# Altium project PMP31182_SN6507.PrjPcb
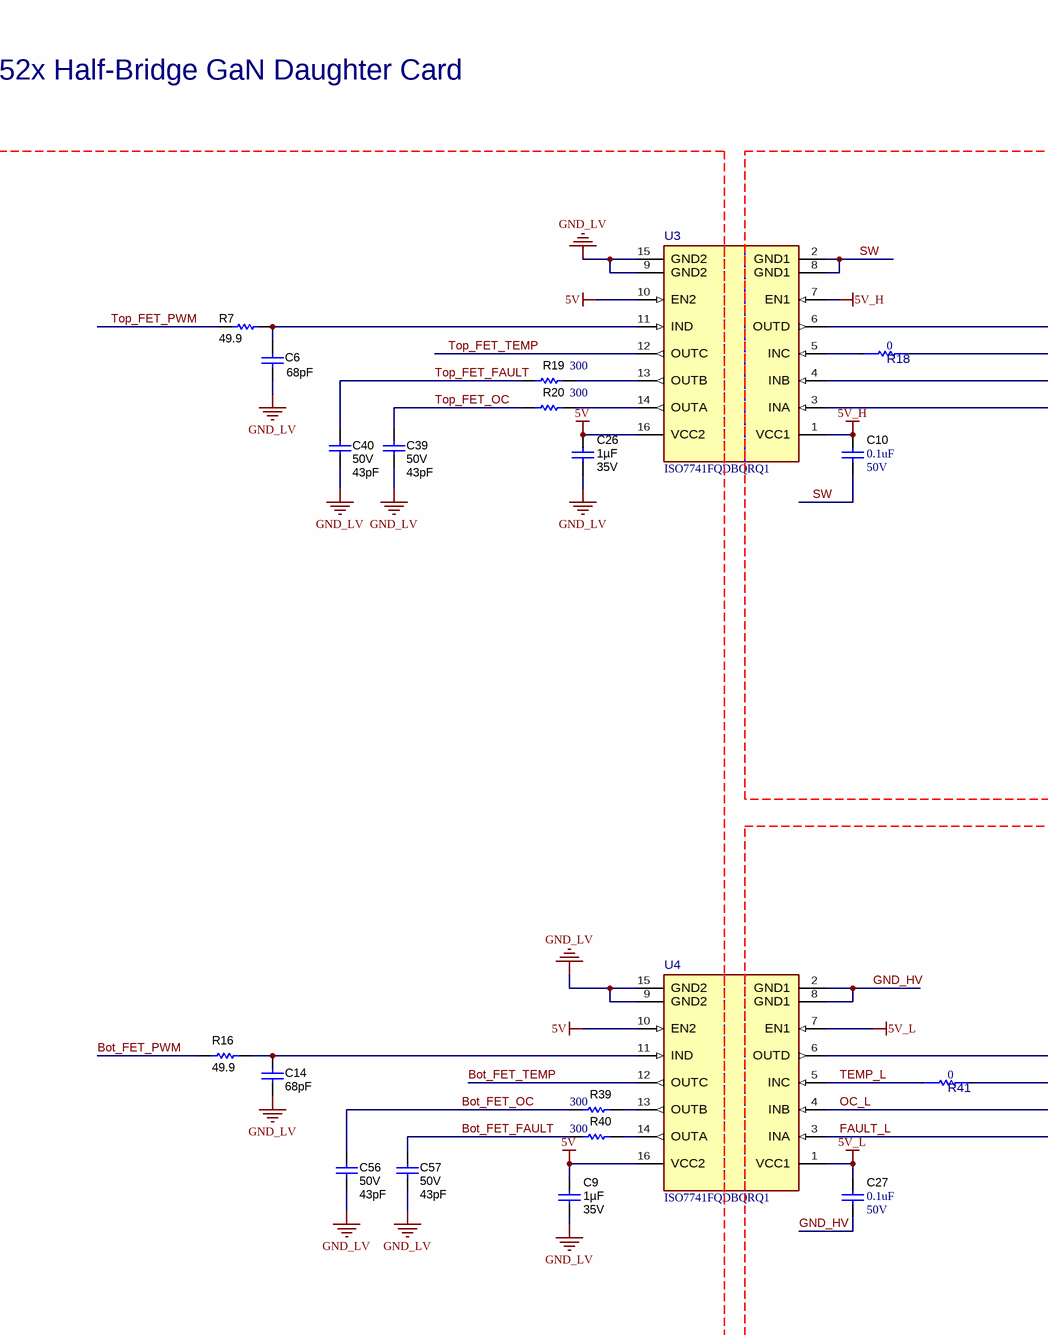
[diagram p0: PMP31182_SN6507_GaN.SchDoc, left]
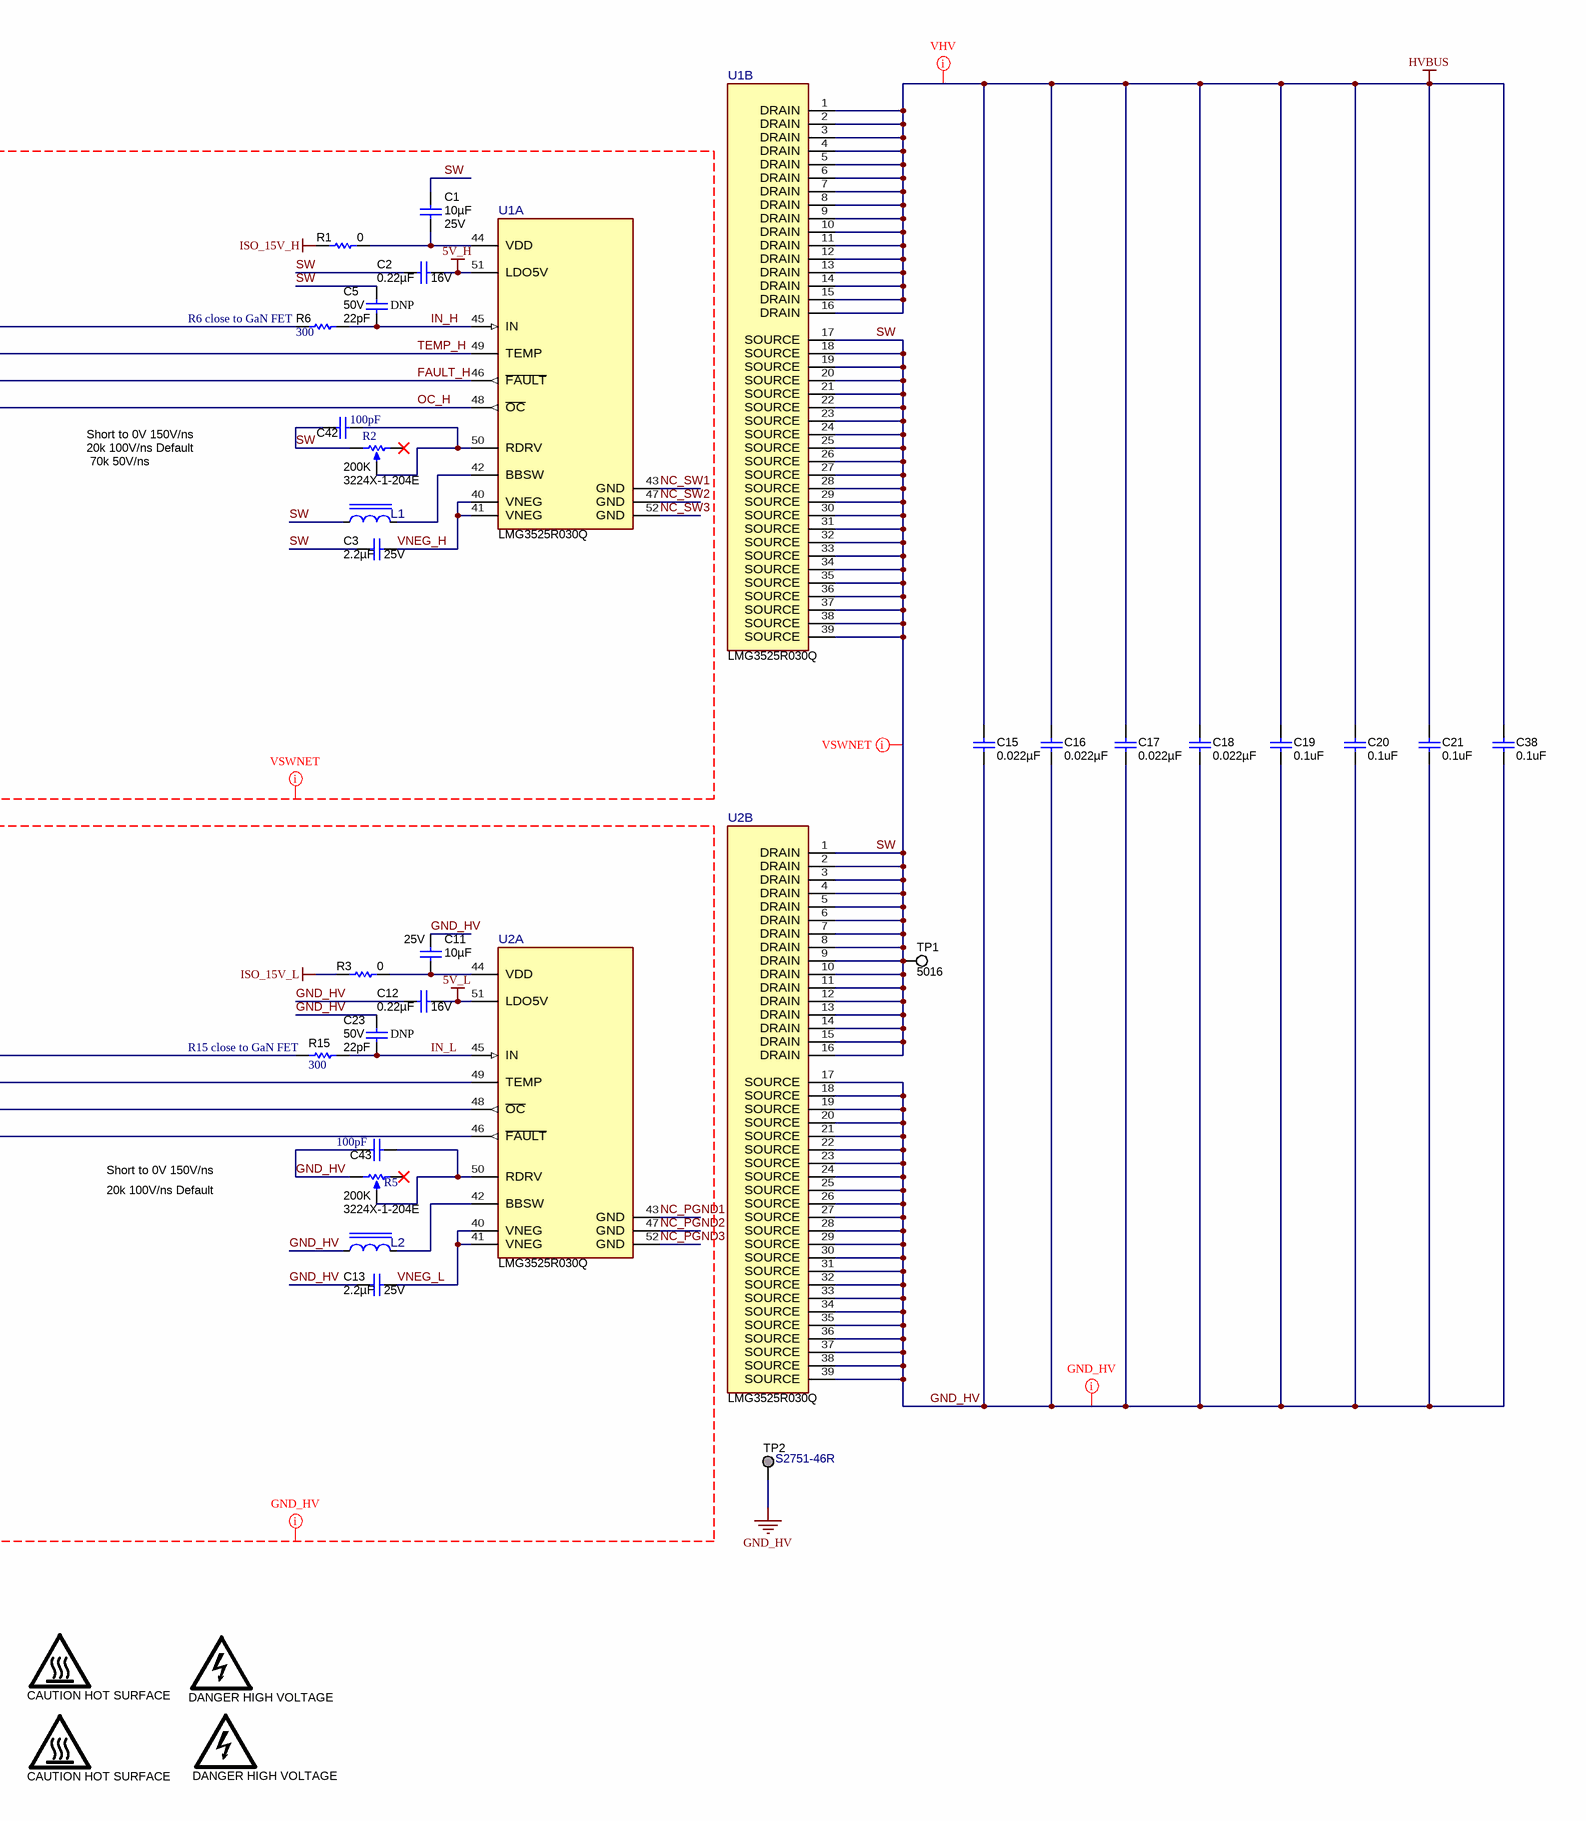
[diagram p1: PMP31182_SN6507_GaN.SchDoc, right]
TID: N/A; TechSupport: http://www.ti.com/support; PRJ_Title: Isolated Bias Power Supply; PRJ_Number: PMP31182; PRJ_Engineer: Prashant Kumar; PRJ_Customer: Public Release; PCB_Layout: Prashant Kumar; CopyrightYear: 2023
3 sheets, 172 parts. Net scope: global (net labels, ports and power ports of the same name join across sheets).
Board file: PMP31182_SN6507_PCB.PcbDoc
Sheets:
  PMP31182_SN6507_GaN.SchDoc
  PMP31182_SN6507_PWM.SchDoc
  PMP31182_SN6507_power_supply.SchDoc

## Sheet PMP31182_SN6507_GaN.SchDoc: SN6507
size A2; Date: Not shown in title block; ApprovedBy: Not shown in title block; CheckedBy: Not shown in title block; Author: Not shown in title block; CompanyName: Not shown in title block; Engineer: Not shown in title block; Organization: Not shown in title block; Address1: Not shown in title block; Address2: Not shown in title block; Address3: Not shown in title block; Address4: Not shown in title block; DocumentNumber: 2; Revision: Use project parameter SCH_Rev; SheetNumber: 2; SheetTotal: 3; PageSetup: Record=PageOptions¦CenterHorizontal=True¦CenterVertical=True¦PrintScale=1.00¦XCorrection=1.00¦YCorrection=1.00¦PrintKind=0¦BorderSize=5000000¦LeftOffset=0¦BottomOffset=0¦Orientation=2¦PaperLength=1000¦PaperWidth=1000¦Scale=100¦PaperSource=15¦PrintQuality=600¦MediaType=1¦DitherType=10¦PaperKind=Letter¦PrintScaleMode=1

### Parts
(Parts that share a designator on the sheet are numbered #1, #2 ... from top to bottom, then left to right.)
C1  VDC_V: 25V  ValueDisplayed: 10µF  [1206_180]  (hidden comment: TMK316AB7106KLHT)
C2  VDC_V: 16V  ValueDisplayed: 0.22µF  [0402]  (hidden comment: GCM155R71C224KE02D)
C3  Cap_F: 2.2µF  VDC_V: 25V  [0805_HV]  (hidden comment: CGA4J3X7R1E225K125AB)
C5  VDC_V: 50V  ValueDisplayed: 22pF  [0402]  (hidden comment: GCM1555C1H220JA16D)
C6  ValueDisplayed: 68pF  [0402]  (hidden comment: C1005C0G1H680J050BA)
C9  VDC_V: 35V  ValueDisplayed: 1µF  [0402]  (hidden comment: GRT155R6YA105KE13D)
C10  VDC_V: 50V  ValueDisplayed: 0.1uF  [0402]  (hidden comment: GCM155R71H104KE02D)
C11  VDC_V: 25V  ValueDisplayed: 10µF  [1206_180]  (hidden comment: TMK316AB7106KLHT)
C12  VDC_V: 16V  ValueDisplayed: 0.22µF  [0402]  (hidden comment: GCM155R71C224KE02D)
C13  Cap_F: 2.2µF  VDC_V: 25V  [0805_HV]  (hidden comment: CGA4J3X7R1E225K125AB)
C14  ValueDisplayed: 68pF  [0402]  (hidden comment: C1005C0G1H680J050BA)
C15  ValueDisplayed: 0.022µF  [1206_190]  (hidden comment: C1206C223KDRACTU)
C16  ValueDisplayed: 0.022µF  [1206_190]  (hidden comment: C1206C223KDRACTU)
C17  ValueDisplayed: 0.022µF  [1206_190]  (hidden comment: C1206C223KDRACTU)
C18  ValueDisplayed: 0.022µF  [1206_190]  (hidden comment: C1206C223KDRACTU)
C19  ValueDisplayed: 0.1uF  [1812_254]  (hidden comment: C1812W104KDRACTU)
C20  ValueDisplayed: 0.1uF  [1812_254]  (hidden comment: C1812W104KDRACTU)
C21  ValueDisplayed: 0.1uF  [1812_254]  (hidden comment: C1812W104KDRACTU)
C23  VDC_V: 50V  ValueDisplayed: 22pF  [0402]  (hidden comment: GCM1555C1H220JA16D)
C26  VDC_V: 35V  ValueDisplayed: 1µF  [0402]  (hidden comment: GRT155R6YA105KE13D)
C27  VDC_V: 50V  ValueDisplayed: 0.1uF  [0402]  (hidden comment: GCM155R71H104KE02D)
C38  ValueDisplayed: 0.1uF  [1812_254]  (hidden comment: C1812W104KDRACTU)
C39  VDC_V: 50V  ValueDisplayed: 43pF  [0402]  (hidden comment: GCQ1555C1H430JB01D)
C40  VDC_V: 50V  ValueDisplayed: 43pF  [0402]  (hidden comment: GCQ1555C1H430JB01D)
C42  ValueDisplayed: 100pF  [0402]  (hidden comment: CGA2B2C0G1H101J050BA)
C43  ValueDisplayed: 100pF  [0402]  (hidden comment: CGA2B2C0G1H101J050BA)
C56  VDC_V: 50V  ValueDisplayed: 43pF  [0402]  (hidden comment: GCQ1555C1H430JB01D)
C57  VDC_V: 50V  ValueDisplayed: 43pF  [0402]  (hidden comment: GCQ1555C1H430JB01D)
L1  MPIA2510V2-4R7-R  [FP-MPIA2510V2-4R7-R_1008-MFG]  (value not drawn)
L2  MPIA2510V2-4R7-R  [FP-MPIA2510V2-4R7-R_1008-MFG]  (value not drawn)
LOGO?#1  CAUTION HOT SURFACE  [IEC_HotSurface_Small]  (no BOM)
LOGO?#2  DANGER HIGH VOLTAGE  [IEC_HighVoltage_Small]  (no BOM)
LOGO?#3  CAUTION HOT SURFACE  [IEC_HotSurface_Small]  (no BOM)
LOGO?#4  DANGER HIGH VOLTAGE  [IEC_HighVoltage_Small]  (no BOM)
R1  ValueDisplayed: 0  [0805_HV]  (hidden comment: CRCW08050000Z0EAHP)
R2  3224X-1-204E  value 200K  [TRIM_3224X]
R3  ValueDisplayed: 0  [0805_HV]  (hidden comment: CRCW08050000Z0EAHP)
R5  3224X-1-204E  value 200K  [TRIM_3224X]
R6  ValueDisplayed: 300  [0402]  (hidden comment: CRCW0402300RJNED)
R7  ValueDisplayed: 49.9  [0402]  (hidden comment: CRCW040249R9FKED)
R15  ValueDisplayed: 300  [0402]  (hidden comment: CRCW0402300RJNED)
R16  ValueDisplayed: 49.9  [0402]  (hidden comment: CRCW040249R9FKED)
R18  Res_ohm: 0  [FP-ERJ-3GEY0R00V_0603-MFG]  (hidden comment: ERJ-3GEY0R00V)
R19  ValueDisplayed: 300  [0402]  (hidden comment: CRCW0402300RJNED)
R20  ValueDisplayed: 300  [0402]  (hidden comment: CRCW0402300RJNED)
R39  ValueDisplayed: 300  [0402]  (hidden comment: CRCW0402300RJNED)
R40  ValueDisplayed: 300  [0402]  (hidden comment: CRCW0402300RJNED)
R41  Res_ohm: 0  [FP-ERJ-3GEY0R00V_0603-MFG]  (hidden comment: ERJ-3GEY0R00V)
TP1  5016  [Testpoint_Keystone_Compact]
TP2  S2751-46R  [Harwin_S2751-46R]
U1  LMG3525R030Q  [RQS0052A-MFG]  (parts A,B of 2)
U2  LMG3525R030Q  [RQS0052A-MFG]  (parts A,B of 2)
U3  ISO7741FQDBQRQ1  [DBQ0016A-MFG]
U4  ISO7741FQDBQRQ1  [DBQ0016A-MFG]

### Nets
5V: C9.1 C26.1 U3.10(EN2) U3.16(VCC2) U4.10(EN2) U4.16(VCC2)
5V_H: C2.1 C10.1 U1.51(LDO5V) U3.1(VCC1) U3.7(EN1)
5V_L: C12.1 C27.1 U2.51(LDO5V) U4.1(VCC1) U4.7(EN1)
GND_HV: C11.1 C12.2 C13.1 C15.2 C16.2 C17.2 C18.2 C19.2 C20.2 C21.2 C23.1 C27.2 C38.2 C43.1 L2.1 R5.1(CCW) TP2.1 U2.17(SOURCE) U2.18(SOURCE) U2.19(SOURCE) U2.20(SOURCE) U2.21(SOURCE) U2.22(SOURCE) U2.23(SOURCE) U2.24(SOURCE) U2.25(SOURCE) U2.26(SOURCE) U2.27(SOURCE) U2.28(SOURCE) U2.29(SOURCE) U2.30(SOURCE) U2.31(SOURCE) U2.32(SOURCE) U2.33(SOURCE) U2.34(SOURCE) U2.35(SOURCE) U2.36(SOURCE) U2.37(SOURCE) U2.38(SOURCE) U2.39(SOURCE) U4.2(GND1) U4.8(GND1)
GND_LV: C6.2 C9.2 C14.1 C26.2 C39.2 C40.2 C56.2 C57.2 U3.9(GND2) U3.15(GND2) U4.9(GND2) U4.15(GND2)
HVBUS: C15.1 C16.1 C17.1 C18.1 C19.1 C20.1 C21.1 C38.1 U1.1(DRAIN) U1.2(DRAIN) U1.3(DRAIN) U1.4(DRAIN) U1.5(DRAIN) U1.6(DRAIN) U1.7(DRAIN) U1.8(DRAIN) U1.9(DRAIN) U1.10(DRAIN) U1.11(DRAIN) U1.12(DRAIN) U1.13(DRAIN) U1.14(DRAIN) U1.15(DRAIN) U1.16(DRAIN)
ISO_15V_H: R1.1
ISO_15V_L: R3.1
Bot_FET_FAULT: C57.1 R40.2
Bot_FET_OC: C56.1 R39.2
Bot_FET_PWM: R16.1
Bot_FET_TEMP: U4.12(OUTC)
FAULT_H: U1.46(~{FAULT}) U3.4(INB)
FAULT_L: U2.46(~{FAULT}) U4.3(INA)
IN_H: C5.2 R6.2 U1.45(IN)
IN_L: C23.2 R15.2 U2.45(IN)
NC_PGND1: U2.43(GND)
NC_PGND2: U2.47(GND)
NC_PGND3: U2.52(GND)
NC_SW1: U1.43(GND)
NC_SW2: U1.47(GND)
NC_SW3: U1.52(GND)
OC_H: U1.48(~{OC}) U3.3(INA)
OC_L: U2.48(~{OC}) U4.4(INB)
SW: C1.2 C2.2 C3.1 C5.1 C10.2 C42.2 L1.1 R2.1(CCW) TP1.1 U1.17(SOURCE) U1.18(SOURCE) U1.19(SOURCE) U1.20(SOURCE) U1.21(SOURCE) U1.22(SOURCE) U1.23(SOURCE) U1.24(SOURCE) U1.25(SOURCE) U1.26(SOURCE) U1.27(SOURCE) U1.28(SOURCE) U1.29(SOURCE) U1.30(SOURCE) U1.31(SOURCE) U1.32(SOURCE) U1.33(SOURCE) U1.34(SOURCE) U1.35(SOURCE) U1.36(SOURCE) U1.37(SOURCE) U1.38(SOURCE) U1.39(SOURCE) U2.1(DRAIN) U2.2(DRAIN) U2.3(DRAIN) U2.4(DRAIN) U2.5(DRAIN) U2.6(DRAIN) U2.7(DRAIN) U2.8(DRAIN) U2.9(DRAIN) U2.10(DRAIN) U2.11(DRAIN) U2.12(DRAIN) U2.13(DRAIN) U2.14(DRAIN) U2.15(DRAIN) U2.16(DRAIN) U3.2(GND1) U3.8(GND1)
TEMP_H: R18.2 U1.49(TEMP)
TEMP_L: R41.1 U4.5(INC)
Top_FET_FAULT: C40.1 R19.2
Top_FET_OC: C39.1 R20.2
Top_FET_PWM: R7.1
Top_FET_TEMP: U3.12(OUTC)
VNEG_H: C3.2 U1.40(VNEG) U1.41(VNEG)
VNEG_L: C13.2 U2.40(VNEG) U2.41(VNEG)
NetC1_1: C1.1 R1.2 U1.44(VDD)
NetC6_1: C6.1 R7.2 U3.11(IND)
NetC11_2: C11.2 R3.2 U2.44(VDD)
NetC14_2: C14.2 R16.2 U4.11(IND)
NetC42_1: C42.1 R2.2(WIPER) U1.50(RDRV)
NetC43_2: C43.2 R5.2(WIPER) U2.50(RDRV)
NetL1_2: L1.2 U1.42(BBSW)
NetL2_2: L2.2 U2.42(BBSW)
NetR6_1: R6.1 U3.6(OUTD)
NetR15_1: R15.1 U4.6(OUTD)
NetR18_1: R18.1 U3.5(INC)
NetR19_1: R19.1 U3.13(OUTB)
NetR20_1: R20.1 U3.14(OUTA)
NetR39_1: R39.1 U4.13(OUTB)
NetR40_1: R40.1 U4.14(OUTA)
NetR41_2: R41.2 U2.49(TEMP)

Not connected (* = marked no-connect by the designer): R2 3(CW)*; R5 3(CW)*

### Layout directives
net class VSWNET: 5V_H, FAULT_H, IN_H, ISO_15V_H, NC_SW1, NC_SW2, NC_SW3, OC_H, SW, TEMP_H, VNEG_H
net class VHV: HVBUS
net class INGND: (no net found under the mark)
net class PGND: 5V_L, FAULT_L, GND_HV, IN_L, ISO_15V_L, NC_PGND1, NC_PGND2, NC_PGND3, OC_L, TEMP_L, VNEG_L

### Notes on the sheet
- LMG352x Half-Bridge GaN Daughter Card
- (near C5) DNP
- (near R6) R6 close to GaN FET
- Short to 0V 150V/ns
- 20k 100V/ns Default
- 70k 50V/ns
- (near R15) R15 close to GaN FET
- (near C23) DNP

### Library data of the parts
C1 C11 = CMP-0750154-1: CAP, CERM, 10 µF, 25 V,+/- 10%, X7R, AEC-Q200 Grade 1, 1206; Manufacturer: Taiyo Yuden; AEC Qualified: Y; SizeZ_mm: 1.8; TaMax_C: 125°C; TaMin_C: -55°C; Cap_Case: 1206; Polarized: N; AEC Grade: 1; SizeY_mm: 1.6; Value: 10uF; SizeX_mm: 3.2; SizeAreaWB_mm2: 10.92; AEC Category: Q200; U/M: EA; SizeArea_mm2: 5.12
C2 C12 = CMP-0078265-1: CAP, CERM, 0.22 µF, 16 V,+/- 10%, X7R, AEC-Q200 Grade 1, 0402; Manufacturer: MuRata; TaMin_C: -55°C; Polarized: N; SizeAreaWB_mm2: 3; U/M: EA; Value: 0.22uF; TaMax_C: 125°C; SizeZ_mm: 0.6; SizeX_mm: 1; SizeY_mm: 0.5; AEC Qualified: Y; Cap_F: 220nF; AEC Category: Q200
C3 C13 = CMP-0007975-2: CAP, CERM, 2.2 uF, 25 V, +/- 10%, X7R, AEC-Q200 Grade 1, 0805; Manufacturer: TDK; TaMin_C: -55°C; Polarized: N; SizeAreaWB_mm2: 6.75; Value1: Unknown; U/M: EA; Value: 2.2uF; TaMax_C: 125°C; SizeZ_mm: 1.45; SizeX_mm: 2; SizeY_mm: 1.25; Cap_Case: 0805; SizeArea_mm2: 2.5; AEC Qualified: Y; AEC Grade: 1; AEC Category: Q200
C5 C23 = CMP-0006348-2: CAP, CERM, 22 pF, 50 V, +/- 5%, C0G/NP0, AEC-Q200 Grade 1, 0402; Manufacturer: MuRata; TaMin_C: -55°C; Polarized: N; SizeAreaWB_mm2: 3; Value1: Unknown; U/M: EA; Value: 22pF; TaMax_C: 125°C; SizeZ_mm: 0.6; SizeX_mm: 1; SizeY_mm: 0.5; AEC Qualified: Y; AEC Category: Q200
C6 C14 = CMP-0006251-2: CAP, CERM, 68 pF, 50 V, +/- 5%, C0G/NP0, 0402; Manufacturer: TDK; Alternate Manufacturer: Murata; Alternate PartNumber: GRM1555C1H680JA01D; TaMin_C: -55°C; Polarized: N; SizeAreaWB_mm2: 3; Value1: Unknown; U/M: EA; Value: 68pF; TaMax_C: 125°C; SizeZ_mm: 0.6; SizeX_mm: 1; SizeY_mm: 0.5; Value2: 50V; AEC Category: Q200
C9 C26 = CMP-0750099-1: CAP, CERM, 1 µF, 35 V,+/- 10%, X5R, AEC-Q200 Grade 3, 0402; Manufacturer: MuRata; AEC Grade: 3; AEC Category: Q200; Value: 1uF; SizeArea_mm2: 0.5; SizeZ_mm: 0.6; AEC Qualified: Y; TaMin_C: -55°C; SizeX_mm: 1; U/M: EA; Polarized: N; TaMax_C: 85°C
C10 C27 = CMP-0006356-2: CAP, CERM, 0.1 uF, 50 V, +/- 10%, X7R, AEC-Q200 Grade 1, 0402; Manufacturer: MuRata; TaMin_C: -55°C; Polarized: N; SizeAreaWB_mm2: 3; Value1: Unknown; U/M: EA; Value: 0.1uF; TaMax_C: 125°C; SizeZ_mm: 0.6; SizeX_mm: 1; SizeY_mm: 0.5; AEC Qualified: Y; Cap_F: 100nF; AEC Category: Q200
C15-C18 = CMP-0084048-1: CAP, CERM, 0.022 µF, 1000 V,+/- 10%, X7R, AEC-Q200 Grade 1, 1206; Manufacturer: Kemet; Polarized: N; CompType: Capacitor; Value: 0.022uF; U/M: EA; Cap_F: 22nF; VDC_V: 1kV; Value2: 1000V; TaMin_C: -55°C; TaMax_C: 125°C; Cap_Case: 1206; SizeArea_mm2: 5.12; SizeAreaWB_mm2: 10.92; SizeX_mm: 3.2; SizeY_mm: 1.6; SizeZ_mm: 1.9; AEC Category: Q200; AEC Qualified: Y; AEC Grade: 1
C19-C21 C38 = CMP-0009326-2: CAP, CERM, 0.1 uF, 1000 V, +/- 10%, X7R, 1812; Manufacturer: Kemet; Polarized: N; Value: 0.1uF; U/M: EA; Cap_F: 100nF; Value1: Unknown; VDC_V: 1kV; Value2: 1000V; TaMin_C: -55°C; TaMax_C: 125°C; Cap_Case: 1812; AEC Category: Q200; SizeArea_mm2: 14.4; SizeAreaWB_mm2: 23.1; SizeX_mm: 4.5; SizeY_mm: 3.2; SizeZ_mm: 2.54
C39 C40 C56 C57 = CMP-0860835-1: CAP, CERM, 43 pF, 50 V,+/- 5%, C0G/NP0, AEC-Q200 Grade 1, 0402; Manufacturer: MuRata; SizeY_mm: 0.5; SizeZ_mm: 0.6; AEC Qualified: Y; AEC Grade: 1; AEC Category: Q200; U/M: EA; Value: 43pF; Polarized: N; TaMin_C: -55°C; SizeAreaWB_mm2: 3; TaMax_C: 125°C
C42 C43 = CMP-0006308-2: CAP, CERM, 100 pF, 50 V, +/- 5%, C0G/NP0, AEC-Q200 Grade 1, 0402; Manufacturer: TDK; TaMin_C: -55°C; Polarized: N; SizeAreaWB_mm2: 3; Value1: Unknown; U/M: EA; Value: 100pF; TaMax_C: 125°C; SizeZ_mm: 0.6; SizeX_mm: 1; SizeY_mm: 0.5; Value2: 50V; AEC Qualified: Y; AEC Category: Q200
L1 L2 = CMP-0090507-1: 4.7µH Shielded Molded Inductor 1.22A 262mOhm Max 1008 (2520 Metric); Manufacturer: Eaton; Material: Metal Composite; Value: 4.7uH; Test Frequency: 1MHz; Isat: 1.8A; DCR_ohm: 0.262; AEC Grade: Grade 1; Tolerance_%: 20%; AEC Qualified: Yes; Self Resonant Frequency: 25MHz; SizeZ_mm: 1.05mm; Shrouded: true
LOGO?#1 LOGO?#3 = CMP-0074837-1: IEC 61010-1 Hot Surface Warning; SymbolCreator: a0412235; Lib Reference: IEC_HotSurface
LOGO?#2 LOGO?#4 = CMP-0074835-1: IEC 61010-1 High Voltage Warning; SymbolCreator: a0412235; Lib Reference: IEC_HighVoltage
R1 R3 = CMP-0020443-3: RES, 0, 5%, 0.333 W, AEC-Q200 Grade 0, 0805; Manufacturer: Vishay-Dale; Power_W: 333mW; TempCo: 200 ppm/C; Value_Code: 0000; Value: 0; EIA_Code: E24; SizeX_mm: 2; SizeY_mm: 1.25; SizeZ_mm: 1.45; Value2: 0.333W; SizeArea_mm2: 2.5; AEC Qualified: Y; AEC Category: Q200; VDC_V: 150V
R2 R5 = CMP-0002064-2: Trimmer, 200 K, 0.25 W, SMD; Manufacturer: Bourns
R6 R15 R19 R20 R39 R40 = CMP-0026902-3: RES, 300, 5%, 0.063 W, AEC-Q200 Grade 0, 0402; Manufacturer: Vishay-Dale; Power_W: 63mW; TempCo: 200 ppm/C; Value_Code: 300R; Value: 300; EIA_Code: E24; SizeX_mm: 1; SizeY_mm: 0.5; SizeZ_mm: 0.6; Value2: 0.063W; AEC Qualified: Y; VDC_V: 50V; AEC Category: Q200; AEC Grade: 0
R7 R16 = CMP-0026404-2: RES, 49.9, 1%, 0.063 W, AEC-Q200 Grade 0, 0402; Manufacturer: Vishay-Dale; Power_W: 63mW; TempCo: 100 ppm/C; Value_Code: 49R9; Value: 49.9; EIA_Code: E96; SizeX_mm: 1; SizeY_mm: 0.5; SizeZ_mm: 0.6; Value2: 0.063W; AEC Qualified: Y; VDC_V: 50V; AEC Category: Q200; AEC Grade: 0
R18 R41 = CMP-0089143-1: 0 Ohms Jumper 0.1W, 1/10W Chip Resistor 0603 (1608 Metric) Automotive AEC-Q200 Thick Film; Manufacturer: Panasonic; SizeZ_mm: 0.55mm; AEC Grade: Grade 0; VDC_V: 75V; TempCo: -100/+600ppm/°C; AEC Qualified: Yes; Power_W: 100mW; Tolerance_%: 5%
TP1 = CMP-0055153-1: Test Point, Compact, SMT; Manufacturer: Keystone; CNHeader: FALSE; Green_Lifecycle: Active; Green_REACh: Passed; CT: TRUE
TP2 = CMP-0003968-1: Test Point, SMT; Manufacturer: Harwin
U1 U2 = CMP-0089968-1: 650-V 30-mΩ GaN FET with Integrated Driver and Protection; Manufacturer: Texas Instruments; Output Voltage: 520V; Nominal Supply Current: 540uA; Min Supply Voltage: 7.5V; Standoff Height: 0mm; AEC Grade: Grade 1; Max Supply Voltage: 18V; Number Of Outputs: 1; AEC Qualified: Yes; TJmax_C: +125°C; SizeZ_mm: 1mm
U3 U4 = CMP-0090469-1: General Purpose Digital Isolator 2500Vrms 4 Channel 100Mbps 85kV/µs CMTI 16-SSOP (0.154", 3.90mm Width); Manufacturer: Texas Instruments; TaMin_C: -40°C; TaMax_C: +125°C; TJmax_C: +150°C; AEC Grade: Grade 1; Min Supply Voltage: 2.25V; AEC Qualified: Yes; Max Supply Voltage: 5.5V; Standoff Height: 0.11mm; Nominal Supply Current: 1.5-18mA; SizeZ_mm: 1.75mm

## Sheet PMP31182_SN6507_PWM.SchDoc: SN6507
size A3
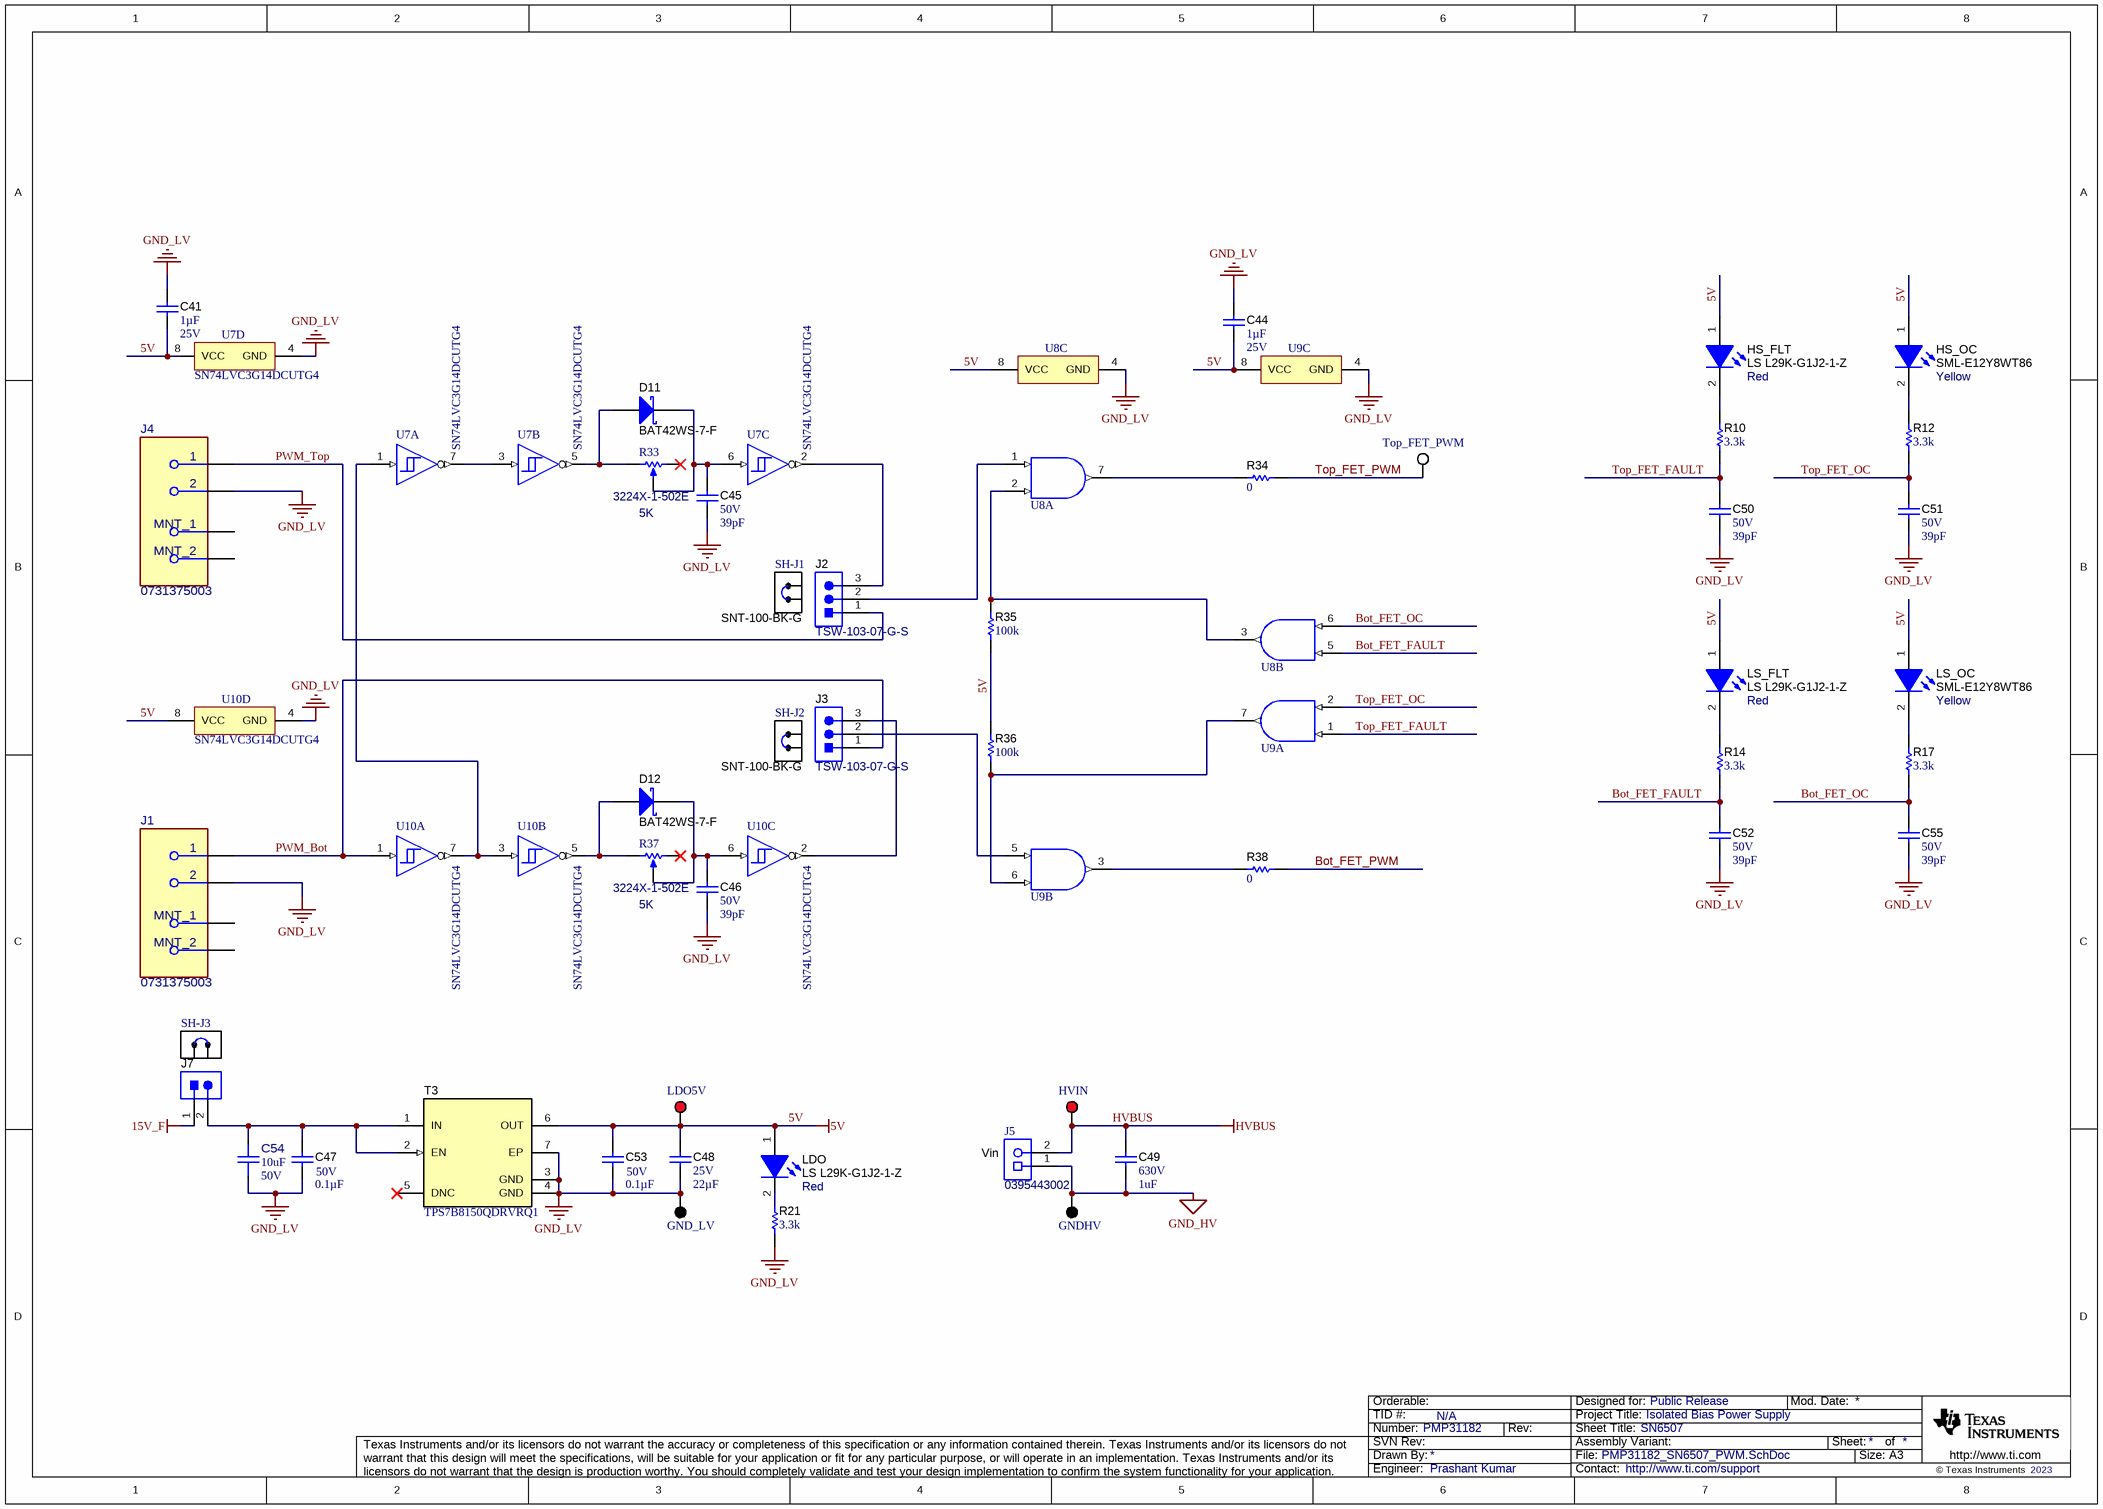
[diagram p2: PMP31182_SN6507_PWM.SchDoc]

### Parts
C41  Cap_F: 1µF  VDC_V: 25V  [0603]  (hidden comment: CGA3E1X7R1E105K080AD)
C44  Cap_F: 1µF  VDC_V: 25V  [0603]  (hidden comment: CGA3E1X7R1E105K080AD)
C45  VDC_V: 50V  ValueDisplayed: 39pF  [0603]  (hidden comment: GRM1885C1H390JA01D)
C46  VDC_V: 50V  ValueDisplayed: 39pF  [0603]  (hidden comment: GRM1885C1H390JA01D)
C47  VDC_V: 50V  ValueDisplayed: 0.1µF  [0603]  (hidden comment: CGA3E3X8R1H104K080AE)
C48  VDC_V: 25V  ValueDisplayed: 22µF  [1210_270]  (hidden comment: GRT32ER61E226KE13L)
C49  VDC_V: 630V  ValueDisplayed: 1uF  [2220_450]  (hidden comment: 2220Y6300105KETWS2)
C50  VDC_V: 50V  ValueDisplayed: 39pF  [0603]  (hidden comment: GRM1885C1H390JA01D)
C51  VDC_V: 50V  ValueDisplayed: 39pF  [0603]  (hidden comment: GRM1885C1H390JA01D)
C52  VDC_V: 50V  ValueDisplayed: 39pF  [0603]  (hidden comment: GRM1885C1H390JA01D)
C53  VDC_V: 50V  ValueDisplayed: 0.1µF  [0603]  (hidden comment: CGA3E3X8R1H104K080AE)
C54  ValueDisplayed: 10uF  VDC_V: 50V  [FP-UMK325AB7106KMHP_1210-MFG]  (hidden comment: UMK325AB7106KMHP)
C55  VDC_V: 50V  ValueDisplayed: 39pF  [0603]  (hidden comment: GRM1885C1H390JA01D)
D11  BAT42WS-7-F  [SOD-323]
D12  BAT42WS-7-F  [SOD-323]
GND_LV  5006  [Keystone5006]  (value not drawn)
GNDHV  5006  [Keystone5006]  (value not drawn)
HS_FLT  LS L29K-G1J2-1-Z  value Red  [LS L29K_Red]
HS_OC  SML-E12Y8WT86  value Yellow  [SML-E1_Yellow]
HVIN  5005  [Keystone5005]  (value not drawn)
J1  0731375003  [FP-0731375003_CONN_BNC_RCPT-MFG]
J2  TSW-103-07-G-S  [TSW-103-07-G-S]
J3  TSW-103-07-G-S  [TSW-103-07-G-S]
J4  0731375003  [FP-0731375003_CONN_BNC_RCPT-MFG]
J5  0395443002  [Molex_0395443002]
J7  TSW-102-07-G-S  [TSW-102-07-G-S]  (value not drawn)
LDO  LS L29K-G1J2-1-Z  value Red  [LS L29K_Red]
LDO5V  5005  [Keystone5005]  (value not drawn)
LS_FLT  LS L29K-G1J2-1-Z  value Red  [LS L29K_Red]
LS_OC  SML-E12Y8WT86  value Yellow  [SML-E1_Yellow]
R10  ValueDisplayed: 3.3k  [0603]  (hidden comment: CRCW06033K30JNEA)
R12  ValueDisplayed: 3.3k  [0603]  (hidden comment: CRCW06033K30JNEA)
R14  ValueDisplayed: 3.3k  [0603]  (hidden comment: CRCW06033K30JNEA)
R17  ValueDisplayed: 3.3k  [0603]  (hidden comment: CRCW06033K30JNEA)
R21  ValueDisplayed: 3.3k  [0603]  (hidden comment: CRCW06033K30JNEA)
R33  3224X-1-502E  value 5K  [TRIM_3224X]
R34  ValueDisplayed: 0  [0603_HV]  (hidden comment: CRCW06030000Z0EA)
R35  ValueDisplayed: 100k  [0603]  (hidden comment: CRCW0603100KJNEAC)
R36  ValueDisplayed: 100k  [0603]  (hidden comment: CRCW0603100KJNEAC)
R37  3224X-1-502E  value 5K  [TRIM_3224X]
R38  ValueDisplayed: 0  [0603_HV]  (hidden comment: CRCW06030000Z0EA)
SH-J1  SNT-100-BK-G  [SNT-100-BK-G]
SH-J2  SNT-100-BK-G  [SNT-100-BK-G]
SH-J3  SNT-100-BK-G  [SNT-100-BK-G]  (value not drawn)
T3  TPS7B8150QDRVRQ1  [DRV0006A]
Top_FET_PWM  5007  [Keystone5007]  (value not drawn)
U7  SN74LVC3G14DCUTG4  [DCU0008A_N]  (parts A,B,C,D of 4)
U8  SN74LVC2G08IDCTRQ1  [DCT0008A_N]  (value not drawn)  (parts A,B,C of 3)
U9  SN74LVC2G08IDCTRQ1  [DCT0008A_N]  (value not drawn)  (parts A,B,C of 3)
U10  SN74LVC3G14DCUTG4  [DCU0008A_N]  (parts A,B,C,D of 4)

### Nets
5V: C41.2 C44.2 C48.1 C53.1 HS_FLT.1(A) HS_OC.1(A) LDO.1(A) LDO5V.1 LS_FLT.1(A) LS_OC.1(A) R35.1 R36.2 T3.6(OUT) U7.8(VCC) U8.8(VCC) U9.8(VCC) U10.8(VCC)
15V_F: J7.1
GND_HV: C49.2 GNDHV.1 J5.1
GND_LV: C41.1 C44.1 C45.2 C46.2 C47.2 C48.2 C50.2 C51.2 C52.2 C53.2 C54.1 C55.2 GND_LV.1 J1.2 J4.2 R21.1 T3.3(GND) T3.4(GND) T3.7(EP) U7.4(GND) U8.4(GND) U9.4(GND) U10.4(GND)
HVBUS: C49.1 HVIN.1 J5.2
Bot_FET_FAULT: C52.1 R14.1 U8.5(2A)
Bot_FET_OC: C55.1 R17.1 U8.6(2B)
Bot_FET_PWM: R38.2
PWM_Bot: J1.1 J3.1 U10.1(1A)
PWM_Top: J2.1 J4.1
Top_FET_FAULT: C50.1 R10.1 U9.1(1A)
Top_FET_OC: C51.1 R12.1 U9.2(1B)
Top_FET_PWM: R34.2 Top_FET_PWM.1
NetC45_1: C45.1 D11.1(K) R33.2(WIPER) U7.6(3A)
NetC46_1: C46.1 D12.1(K) R37.2(WIPER) U10.6(3A)
NetC47_1: C47.1 C54.2 J7.2 T3.1(IN) T3.2(EN)
NetD11_2: D11.2(A) R33.1(CCW) U7.5(2Y)
NetD12_2: D12.2(A) R37.1(CCW) U10.5(2Y)
NetHS_FLT_2: HS_FLT.2(K) R10.2
NetHS_OC_2: HS_OC.2(K) R12.2
NetJ2_2: J2.2 U8.1(1A)
NetJ2_3: J2.3 U7.2(3Y)
NetJ3_2: J3.2 U9.5(2A)
NetJ3_3: J3.3 U10.2(3Y)
NetLDO_2: LDO.2(K) R21.2
NetLS_FLT_2: LS_FLT.2(K) R14.2
NetLS_OC_2: LS_OC.2(K) R17.2
NetR34_1: R34.1 U8.7(1Y)
NetR35_2: R35.2 U8.2(1B) U8.3(2Y)
NetR36_1: R36.1 U9.6(2B) U9.7(1Y)
NetR38_1: R38.1 U9.3(2Y)
NetU7_1: U7.1(1A) U10.3(2A) U10.7(1Y)
NetU7_3: U7.3(2A) U7.7(1Y)

Not connected (* = marked no-connect by the designer): J1 3(MNT_1) 4(MNT_2); J4 3(MNT_1) 4(MNT_2); R33 3(CW)*; R37 3(CW)*; T3 5(DNC)*

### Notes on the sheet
- (near J5) Vin

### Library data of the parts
C41 C44 = CMP-0082523-1: CAP, CERM, 1 µF, 25 V,+/- 10%, X7R, AEC-Q200 Grade 1, 0603; Manufacturer: TDK; SizeAreaWB_mm2: 4.68; SizeArea_mm2: 1.28; AEC Qualified: Y; AEC Category: Q200; Value: 1uF; TaMax_C: 125°C; SizeZ_mm: 1; Polarized: N; TaMin_C: -55°C; SizeY_mm: 0.8; U/M: EA; SizeX_mm: 1.6
C45 C46 C50-C52 C55 = CMP-0007214-4: CAP, CERM, 39 pF, 50 V, +/- 5%, C0G/NP0, 0603; Manufacturer: MuRata; TaMin_C: -55°C; Polarized: N; SizeAreaWB_mm2: 4.68; Value1: Unknown; U/M: EA; Value: 39pF; TaMax_C: 125°C; SizeZ_mm: 1; SizeX_mm: 1.6; SizeY_mm: 0.8; SizeArea_mm2: 1.28; AEC Category: Q200
C47 C53 = CMP-0079911-1: CAP, CERM, 0.1 µF, 50 V,+/- 10%, X8R, AEC-Q200 Grade 0, 0603; Manufacturer: TDK; Cap_F: 100nF; SizeAreaWB_mm2: 4.68; SizeArea_mm2: 1.28; AEC Qualified: Y; AEC Category: Q200; Value: 0.1uF; TaMax_C: 150°C; SizeZ_mm: 1; AEC Grade: 0; Polarized: N; TaMin_C: -55°C; SizeY_mm: 0.8; U/M: EA; SizeX_mm: 1.6
C48 = CMP-0084059-1: CAP, CERM, 22 µF, 25 V,+/- 10%, X5R, AEC-Q200 Grade 3, 1210; Manufacturer: MuRata; SizeAreaWB_mm2: 14.7; SizeArea_mm2: 8; AEC Qualified: Y; AEC Category: Q200; Value: 22uF; TaMax_C: 85°C; SizeZ_mm: 2.7; AEC Grade: 3; Polarized: N; TaMin_C: -55°C; SizeY_mm: 2.5; U/M: EA; SizeX_mm: 3.2; Cap_Case: 1210
C49 = CMP-0064919-2: CAP, CERM, 1 uF, 630 V,+/- 10%, X7R, AEC-Q200 Grade 1, 2220; Manufacturer: Knowles Capacitors; PartNumber: 2220Y6300105KXTWS2; TaMin_C: -55°C; Polarized: N; SizeAreaWB_mm2: 53.9; Value1: Unknown; U/M: EA; Value: 1uF; TaMax_C: 125°C; SizeZ_mm: 4.5; SizeX_mm: 5.7; SizeY_mm: 5; Cap_Case: 2220; SizeArea_mm2: 28.5; AEC Qualified: Y; Cap_F: 1µF; AEC Grade: 1; AEC Category: Q200
C54 = CMP-0089980-1: 10µF ±10% 50V Ceramic Capacitor X7R 1210 (3225 Metric); Manufacturer: Taiyo Yuden; SizeZ_mm: 2.8mm; AEC Qualified: Yes; AEC Grade: Grade 1; TempCo: 15%
D11 D12 = CMP-0028447-2: Diode, Schottky, 30 V, 0.2 A, SOD-323; Manufacturer: Diodes Inc.; SizeZ_mm: 1; AEC Category: Q101; Green_REACh: Incomplete; Green_Lifecycle: Not Set; Vr_V: 30V; Vf_V: 1V; Io_A: 200mA; SizeY_mm: 1.35; Value1: 0.2A; Value: 30V; SizeArea_mm2: 3.645; SizeX_mm: 2.7; SizeAreaWB_mm2: 8.695
GND_LV GNDHV = CMP-0055143-1: Test Point, Compact, Black, TH; Manufacturer: Keystone; CNHeader: FALSE; Green_Lifecycle: Active; Green_REACh: Passed; ContactFinish: Silver; CT: TRUE
HS_FLT LDO LS_FLT = CMP-0002902-2: LED, Red, SMD; Manufacturer: OSRAM; Io_A: 20mA; Vr_V: 12V; Tjmax_C: 110°C; Value1: W; Angle: 160; Vf_V: 1.8V
HS_OC LS_OC = CMP-0002977-1: LED, Yellow, SMD; Manufacturer: Rohm; Io_A: 20mA; Power_TotalModule: 54mW; Vr_V: 5V; Tjmax_C: 85°C; Value1: 0.054W; U/M: EA; Ir_A: 10µA; Vf_V: 2.2V; LuminousIntensity_IV: 63
HVIN LDO5V = CMP-0055142-1: Test Point, Compact, Red, TH; Manufacturer: Keystone; CNHeader: FALSE; Green_Lifecycle: Active; Green_REACh: Passed; ContactFinish: Silver; CT: TRUE
J1 J4 = CMP-0095823-1: Connector BNC Female 0Hz To 2GHz 50 Ohm Solder Right Angle Through Hole Gold Tray; Manufacturer: Molex; Voltage_V: 500V; Impedance: 50Ω; Standoff Height: 0.57mm; Is Female: yes; ContactFinish: Gold,Tin,Nickel; Dielectric Material: Polypropylene; SizeZ_mm: 13.33mm; AEC Qualified: No
J2 J3 = CMP-0075407-2: Header, 100mil, 3x1, Gold, TH; Manufacturer: Samtec; Pitch_mm: 2.54; Cert_VDE: N; Gender: Male; Cert_CSA: Y; Voltage_V: 550V; Green_REACh: Passed; Current_A: 6.3A; Green_Lifecycle: Active; Row_Count: 1
J5 = CMP-0055342-2: Terminal Block, 5.08mm, 2x1, TH; Manufacturer: Molex; Current_A: 15A; Green_Lifecycle: Not Set; Gender: Female; Green_REACh: Incomplete; Voltage_V: 300V; Row_Count: 1; Pitch_mm: 5.08
J7 = CMP-0075405-2: Header, 100mil, 2x1, Gold, TH; Manufacturer: Samtec; Pitch_mm: 2.54; Cert_VDE: N; Gender: Male; Cert_CSA: Y; Voltage_V: 550V; Green_REACh: Passed; Current_A: 6.3A; Green_Lifecycle: Active; Row_Count: 1
R10 R12 R14 R17 R21 = CMP-0025797-4: RES, 3.3 k, 5%, 0.1 W, AEC-Q200 Grade 0, 0603; Manufacturer: Vishay-Dale; Power_W: 100mW; TempCo: 200 ppm/C; Value_Code: 3k30; Value: 3.3k; EIA_Code: E24; SizeX_mm: 1.6; SizeY_mm: 0.8; SizeZ_mm: 1; Value2: 0.1W; SizeArea_mm2: 1.28; AEC Qualified: Y; VDC_V: 75V; AEC Category: Q200; AEC Grade: 0
R33 R37 = CMP-0002062-2: Trimmer, 5 K, 0.25 W, SMD; Manufacturer: Bourns
R34 R38 = CMP-0025697-4: RES, 0, 5%, 0.1 W, AEC-Q200 Grade 0, 0603; Manufacturer: Vishay-Dale; Power_W: 100mW; TempCo: 200 ppm/C; Value_Code: 0000; Value: 0; EIA_Code: E24; SizeX_mm: 1.6; SizeY_mm: 0.8; SizeZ_mm: 1; Value2: 0.1W; SizeArea_mm2: 1.28; AEC Qualified: Y; VDC_V: 75V; AEC Category: Q200
R35 R36 = CMP-0082530-1: RES, 100 k, 5%, 0.1 W, 0603; Manufacturer: Vishay-Dale; Power_W: 100mW; TempCo: 200 ppm/C; SizeAreaWB_mm2: 4.68; Value: 100k; EIA_Code: E24; SizeX_mm: 1.6; SizeY_mm: 0.8; SizeZ_mm: 1; Value2: 0.1W; SizeArea_mm2: 1.28; AEC Qualified: N; VDC_V: 75V; AEC Category: Q200
SH-J1-SH-J3 = CMP-0003623-3: Shunt, 100mil, Gold plated, Black; Alternate PartNumber: 969102-0000-DA; Manufacturer: Samtec; Alternate Manufacturer: 3M; Value: 1x2
T3 = CMP-0086086-2: 150-mA High-Voltage Ultralow-IQ Low-Dropout Regulator, DRV0006A (WSON-6); Alternate Manufacturer: Texas Instruments; AEC Category: Q200; CompType: IC; SizeArea_mm2: 4; SizeY_mm: 2; SizeAreaWB_mm2: 9; AEC Qualified: Y; SizeZ_mm: 0.8
Top_FET_PWM = CMP-0055144-1: Test Point, Compact, White, TH; Manufacturer: Keystone; CNHeader: FALSE; Green_Lifecycle: Active; Green_REACh: Passed; ContactFinish: Silver; CT: TRUE
U7 U10 = CMP-0051969-2: Triple Schmitt-Trigger Inverter, DCU0008A (VSSOP-8); Manufacturer: Texas Instruments; Output Type: CMOS; Logic: Inverting; tpd @ Nom Voltage(Max)(ns): 9.2,5.7,5.4,4.3; Bits(#): 3; ICC @ Nom Voltage(Max)(mA): 0.01; Output Drive (IOL/IOH)(Max)(mA): 32/-32; F @ Nom Voltage(Max)(Mhz): 150; Voltage(Nom)(V): 1.8,2.5,3.3,5; Input Type: CMOS/TTL; Schmitt Trigger: Yes; VCC(Max)(V): 5.5; VCC(Min)(V): 1.65; Technology Family: LVC; Rating: Catalog; 3-State Output: No; AEC Category: Q200; AEC Qualified: N; CompType: IC; SizeAreaWB_mm2: 12.6; SizeArea_mm2: 6.4; SizeX_mm: 3.2; SizeY_mm: 2.0; SizeZ_mm: 0.9
U8 U9 = CMP-0051803-1: Automotive Catalog Dual 2-Input Positive-AND Gate, DCT0008A, LARGE T&R; Manufacturer: Texas Instruments; Generic Part Number: SN74LVC2G08-Q1; F @ Nom Voltage(Max)(Mhz): 150; ICC @ Nom Voltage(Max)(mA): 0.01; Input Type: CMOS/TTL; Output Type: CMOS; Logic: True; VCC(Max)(V): 5.5; Technology Family: LVC; Schmitt Trigger: No; Bits(#): 2; tpd @ Nom Voltage(Max)(ns): 9,5.1,4.7,3.8; VCC(Min)(V): 1.65; Voltage(Nom)(V): 1.8,2.5,3.3,5; Output Drive (IOL/IOH)(Max)(mA): 32/-32

## Sheet PMP31182_SN6507_power_supply.SchDoc: SN6507
size A3; Date: Not shown in title block; ApprovedBy: Not shown in title block; CheckedBy: Not shown in title block; Author: Not shown in title block; CompanyName: Not shown in title block; Engineer: Not shown in title block; Organization: Not shown in title block; Address1: Not shown in title block; Address2: Not shown in title block; Address3: Not shown in title block; Address4: Not shown in title block; DocumentNumber: 1; Revision: Use project parameter SCH_Rev; SheetNumber: 1; SheetTotal: 1; PageSetup: Record=PageOptions¦CenterHorizontal=True¦CenterVertical=True¦PrintScale=0.69¦XCorrection=1.00¦YCorrection=1.00¦PrintKind=0¦BorderSize=5000000¦LeftOffset=0¦BottomOffset=0¦Orientation=2¦PaperLength=1000¦PaperWidth=1000¦Scale=100¦PaperSource=15¦PrintQuality=600¦MediaType=1¦DitherType=10¦PaperKind=Letter¦PrintScaleMode=1
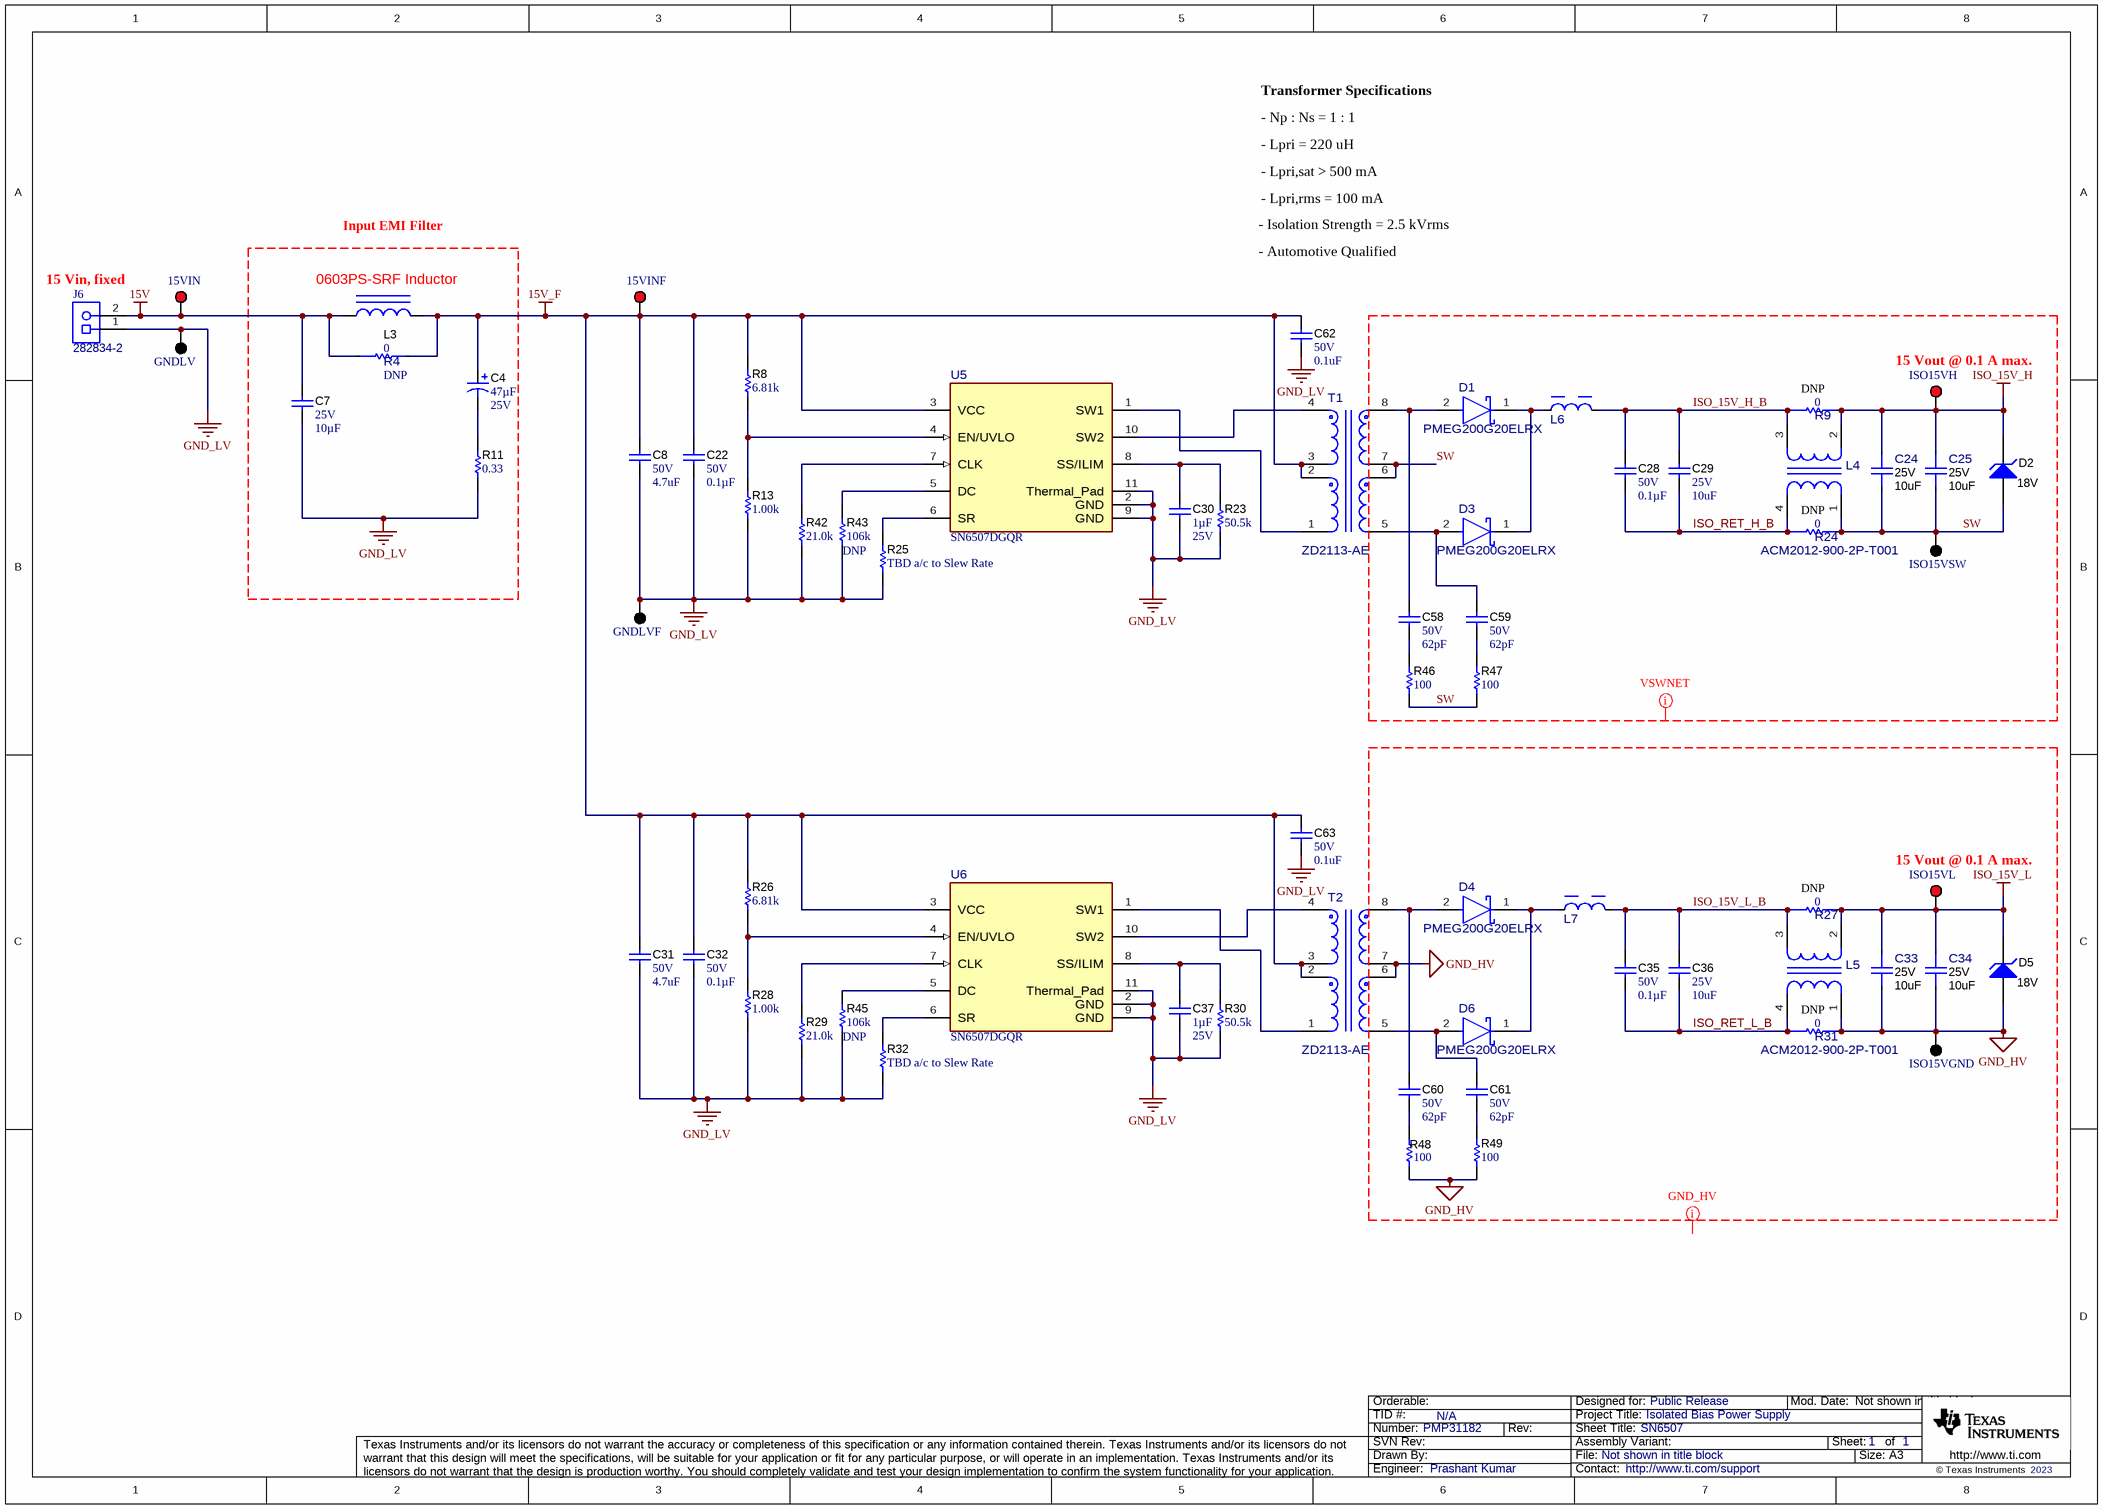
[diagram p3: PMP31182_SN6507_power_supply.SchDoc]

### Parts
15VIN  5005  [Keystone5005]  (value not drawn)
15VINF  5005  [Keystone5005]  (value not drawn)
C4  ValueDisplayed: 47µF  VDC_V: 25V  [HXB_F61]  (hidden comment: HHXC250ARA470MF61G)
C7  VDC_V: 25V  ValueDisplayed: 10µF  [1206_180]  (hidden comment: C1206C106J3RACAUTO)
C8  VDC_V: 50V  ValueDisplayed: 4.7uF  [1210_280]  (hidden comment: CGA6P3X7R1H475M250AB)
C22  VDC_V: 50V  ValueDisplayed: 0.1µF  [0603]  (hidden comment: CGA3E3X8R1H104K080AE)
C24  VDC_V: 25V  ValueDisplayed: 10uF  [FP-CGA4J1X7S1E106K125AC_0805-MFG]  (hidden comment: CGA4J1X7S1E106K125AC)
C25  VDC_V: 25V  ValueDisplayed: 10uF  [FP-CGA4J1X7S1E106K125AC_0805-MFG]  (hidden comment: CGA4J1X7S1E106K125AC)
C28  VDC_V: 50V  ValueDisplayed: 0.1µF  [0603]  (hidden comment: CGA3E3X8R1H104K080AE)
C29  VDC_V: 25V  ValueDisplayed: 10uF  [1210_280]  (hidden comment: CGA6P1X7R1E106M250AC)
C30  Cap_F: 1µF  VDC_V: 25V  [0603]  (hidden comment: GCM188R71E105KA64D)
C31  VDC_V: 50V  ValueDisplayed: 4.7uF  [1210_280]  (hidden comment: CGA6P3X7R1H475M250AB)
C32  VDC_V: 50V  ValueDisplayed: 0.1µF  [0603]  (hidden comment: CGA3E3X8R1H104K080AE)
C33  VDC_V: 25V  ValueDisplayed: 10uF  [FP-CGA4J1X7S1E106K125AC_0805-MFG]  (hidden comment: CGA4J1X7S1E106K125AC)
C34  VDC_V: 25V  ValueDisplayed: 10uF  [FP-CGA4J1X7S1E106K125AC_0805-MFG]  (hidden comment: CGA4J1X7S1E106K125AC)
C35  VDC_V: 50V  ValueDisplayed: 0.1µF  [0603]  (hidden comment: CGA3E3X8R1H104K080AE)
C36  VDC_V: 25V  ValueDisplayed: 10uF  [1210_280]  (hidden comment: CGA6P1X7R1E106M250AC)
C37  Cap_F: 1µF  VDC_V: 25V  [0603]  (hidden comment: GCM188R71E105KA64D)
C58  VDC_V: 50V  ValueDisplayed: 62pF  [0402]  (hidden comment: GRM1555C1H620JA01D)
C59  VDC_V: 50V  ValueDisplayed: 62pF  [0402]  (hidden comment: GRM1555C1H620JA01D)
C60  VDC_V: 50V  ValueDisplayed: 62pF  [0402]  (hidden comment: GRM1555C1H620JA01D)
C61  VDC_V: 50V  ValueDisplayed: 62pF  [0402]  (hidden comment: GRM1555C1H620JA01D)
C62  VDC_V: 50V  ValueDisplayed: 0.1uF  [0402]  (hidden comment: C1005X6S1H104K050BB)
C63  VDC_V: 50V  ValueDisplayed: 0.1uF  [0402]  (hidden comment: C1005X6S1H104K050BB)
D1  PMEG200G20ELRX  [FP-PMEG6020ELRX_SOD123W-MFG]
D2  value 18V  [SOD-123]  (hidden comment: BZT52C18-7-F)
D3  PMEG200G20ELRX  [FP-PMEG6020ELRX_SOD123W-MFG]
D4  PMEG200G20ELRX  [FP-PMEG6020ELRX_SOD123W-MFG]
D5  value 18V  [SOD-123]  (hidden comment: BZT52C18-7-F)
D6  PMEG200G20ELRX  [FP-PMEG6020ELRX_SOD123W-MFG]
GNDLV  5006  [Keystone5006]  (value not drawn)
GNDLVF  5006  [Keystone5006]  (value not drawn)
ISO15VGND  5006  [Keystone5006]  (value not drawn)
ISO15VH  5005  [Keystone5005]  (value not drawn)
ISO15VL  5005  [Keystone5005]  (value not drawn)
ISO15VSW  5006  [Keystone5006]  (value not drawn)
J6  282834-2  [TEC_282834-2]
L3  0603PS-SRF Inductor  [0603AF]
L4  ACM2012-900-2P-T001  [FP-ACM2012-900-2P-T001_SMD4-MFG]
L5  ACM2012-900-2P-T001  [FP-ACM2012-900-2P-T001_SMD4-MFG]
L6  74438335330  [FP-74438335330_SMT2_3MM0_3MM0-MFG]  (value not drawn)
L7  74438335330  [FP-74438335330_SMT2_3MM0_3MM0-MFG]  (value not drawn)
R4  Res_ohm: 0  [FP-ERJ-3GEY0R00V_0603-MFG]  (hidden comment: ERJ-3GEY0R00V)
R8  ValueDisplayed: 6.81k  [0603]  (hidden comment: RT0603BRD076K81L)
R9  Res_ohm: 0  [FP-ERJ-3GEY0R00V_0603-MFG]  (hidden comment: ERJ-3GEY0R00V)
R11  ValueDisplayed: 0.33  [0603]  (hidden comment: ERJ-3RQFR33V)
R13  ValueDisplayed: 1.00k  [0603]  (hidden comment: RT0603BRD071KL)
R23  ValueDisplayed: 50.5k  [0603]  (hidden comment: RT0603BRD0750K5L)
R24  Res_ohm: 0  [FP-ERJ-3GEY0R00V_0603-MFG]  (hidden comment: ERJ-3GEY0R00V)
R25  ValueDisplayed: TBD a/c to Slew Rate  [0603]
R26  ValueDisplayed: 6.81k  [0603]  (hidden comment: RT0603BRD076K81L)
R27  Res_ohm: 0  [FP-ERJ-3GEY0R00V_0603-MFG]  (hidden comment: ERJ-3GEY0R00V)
R28  ValueDisplayed: 1.00k  [0603]  (hidden comment: RT0603BRD071KL)
R29  ValueDisplayed: 21.0k  [0603]  (hidden comment: RC0603FR-0721KL)
R30  ValueDisplayed: 50.5k  [0603]  (hidden comment: RT0603BRD0750K5L)
R31  Res_ohm: 0  [FP-ERJ-3GEY0R00V_0603-MFG]  (hidden comment: ERJ-3GEY0R00V)
R32  ValueDisplayed: TBD a/c to Slew Rate  [0603]
R42  ValueDisplayed: 21.0k  [0603]  (hidden comment: RC0603FR-0721KL)
R43  ValueDisplayed: 106k  [0603]  (hidden comment: RT0603BRD07106KL)
R45  ValueDisplayed: 106k  [0603]  (hidden comment: RT0603BRD07106KL)
R46  ValueDisplayed: 100  [0402]  (hidden comment: RMCF0402JT100R)
R47  ValueDisplayed: 100  [0402]  (hidden comment: RMCF0402JT100R)
R48  ValueDisplayed: 100  [0402]  (hidden comment: RMCF0402JT100R)
R49  ValueDisplayed: 100  [0402]  (hidden comment: RMCF0402JT100R)
T1  ZD2113-AE  [FP-TX1-ZB1459-BED_SMT8_8MM1_10MM0-MFG]
T2  ZD2113-AE  [FP-TX1-ZB1459-BED_SMT8_8MM1_10MM0-MFG]
U5  SN6507DGQR  [DGQ0010D-C01-MFG]
U6  SN6507DGQR  [DGQ0010D-C01-MFG]

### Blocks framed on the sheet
Input EMI Filter: C4 C7 L3 R4 R11

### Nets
15V: 15VIN.1 C7.1 J6.2 L3.1 R4.1
15V_F: 15VINF.1 C4.1(+) C8.1 C22.1 C31.1 C32.1 C62.1 C63.1 L3.2 R4.2 R8.2 R26.2 T1.2 T1.3 T2.2 T2.3 U5.3(VCC) U6.3(VCC)
GND_HV: C33.2 C34.2 D5.2(A) ISO15VGND.1 L5.1 R31.2 R48.1 R49.1 T2.6 T2.7
GND_LV: C7.2 C8.2 C22.2 C30.2 C31.2 C32.2 C37.2 C62.2 C63.2 GNDLV.1 GNDLVF.1 J6.1 R11.1 R13.1 R23.1 R25.1 R28.1 R29.1 R30.1 R32.1 R42.1 R43.1 R45.1 U5.2(GND) U5.9(GND) U5.11(Thermal_Pad) U6.2(GND) U6.9(GND) U6.11(Thermal_Pad)
ISO_15V_H: C24.1 C25.1 D2.1(K) ISO15VH.1 L4.2 R9.2
ISO_15V_L: C33.1 C34.1 D5.1(K) ISO15VL.1 L5.2 R27.2
ISO_15V_H_B: C28.1 C29.1 L4.3 L6.2 R9.1
ISO_15V_L_B: C35.1 C36.1 L5.3 L7.2 R27.1
ISO_RET_H_B: C28.2 C29.2 L4.4 R24.1
ISO_RET_L_B: C35.2 C36.2 L5.4 R31.1
SW: C24.2 C25.2 D2.2(A) ISO15VSW.1 L4.1 R24.2 R46.1 R47.1 T1.6 T1.7
NetC4_2: C4.2(-) R11.2
NetC30_1: C30.1 R23.2 U5.8(SS/ILIM)
NetC37_1: C37.1 R30.2 U6.8(SS/ILIM)
NetC58_1: C58.1 D1.2(ANODE) T1.8
NetC58_2: C58.2 R46.2
NetC59_1: C59.1 D3.2(ANODE) T1.5
NetC59_2: C59.2 R47.2
NetC60_1: C60.1 D4.2(ANODE) T2.8
NetC60_2: C60.2 R48.2
NetC61_1: C61.1 D6.2(ANODE) T2.5
NetC61_2: C61.2 R49.2
NetD1_1: D1.1(CATHODE) D3.1(CATHODE) L6.1
NetD4_1: D4.1(CATHODE) D6.1(CATHODE) L7.1
NetR8_1: R8.1 R13.2 U5.4(EN/UVLO)
NetR25_2: R25.2 U5.6(SR)
NetR26_1: R26.1 R28.2 U6.4(EN/UVLO)
NetR29_2: R29.2 U6.7(CLK)
NetR32_2: R32.2 U6.6(SR)
NetR42_2: R42.2 U5.7(CLK)
NetR43_2: R43.2 U5.5(DC)
NetR45_2: R45.2 U6.5(DC)
NetT1_1: T1.1 U5.1(SW1)
NetT1_4: T1.4 U5.10(SW2)
NetT2_1: T2.1 U6.1(SW1)
NetT2_4: T2.4 U6.10(SW2)

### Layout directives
net class VSWNET: ISO_15V_H, ISO_15V_H_B, ISO_RET_H_B, SW
net class PGND: (no net found under the mark)

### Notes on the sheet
- Transformer Specifications
- - Np : Ns = 1 : 1
- - Lpri = 220 uH
- - Lpri,sat > 500 mA
- - Isolation Strength = 2.5 kVrms
- - Lpri,rms = 100 mA
- 15 Vin, fixed
- - Automotive Qualified
- (near R4) DNP
- (near ISO15VH) 15 Vout @ 0.1 A max.
- (near R9) DNP
- DNP
- (near R43) DNP
- (near R27) DNP
- (near ISO15VL) 15 Vout @ 0.1 A max.
- (near R45) DNP

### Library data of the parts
15VIN 15VINF = CMP-0055142-2: Test Point, Compact, Red, TH; Manufacturer: Keystone Electronics; CNHeader: FALSE; Green_Lifecycle: Active; Green_REACh: Passed; ContactFinish: Silver; CT: TRUE
C4 = CMP-0750159-1: CAP, AL, 47 µF, 25 V, +/- 20%, 0.05 ohm, AEC-Q200 Grade 1, SMD; Manufacturer: Chemi-Con; TaMin_C: -55°C; Cap_Case: 6.3x5.8mm; CompType: Capacitor; TaMax_C: 125°C; U/M: EA; Value: 47uF; AEC Grade: 1; AEC Category: Q200; AEC Qualified: Y; ESR_ohm: 0.05
C7 = CMP-0081062-1: CAP, CERM, 10 µF, 25 V,+/- 5%, X7R, AEC-Q200 Grade 1, 1206; Manufacturer: Kemet; TaMin_C: -55°C; Polarized: N; SizeAreaWB_mm2: 10.92; U/M: EA; Value: 10uF; TaMax_C: 125°C; SizeZ_mm: 1.8; SizeX_mm: 3.2; SizeY_mm: 1.6; SizeArea_mm2: 5.12; AEC Qualified: Y; AEC Grade: 1; AEC Category: Q200
C8 C31 = CMP-0009163-2: CAP, CERM, 4.7 uF, 50 V, +/- 20%, X7R, AEC-Q200 Grade 1, 1210; Manufacturer: TDK; TaMin_C: -55°C; Polarized: N; SizeAreaWB_mm2: 14.7; Value1: Unknown; U/M: EA; Value: 4.7uF; TaMax_C: 125°C; SizeZ_mm: 2.8; SizeX_mm: 3.2; SizeY_mm: 2.5; Cap_Case: 1210; SizeArea_mm2: 8; AEC Qualified: Y; Cap_F: 4.7µF; AEC Grade: 1; AEC Category: Q200
C22 C28 C32 C35 = CMP-0079911-1: as C47 on sheet PMP31182_SN6507_PWM
C24 C25 C33 C34 = CMP-0091069-1: Cap Ceramic 10uF 25V X7S 10% Pad SMD 0805 +125°C Automotive T/R; Manufacturer: TDK Corporation; AEC Qualified: Yes; AEC Grade: Grade 1; Value: 10µF; Tolerance_%: 0.1%; SizeZ_mm: 1.45mm; TempCo: 22%
C29 C36 = CMP-0009155-2: CAP, CERM, 10 uF, 25 V, +/- 20%, X7R, AEC-Q200 Grade 1, 1210; Manufacturer: TDK; TaMin_C: -55°C; Polarized: N; SizeAreaWB_mm2: 14.7; Value1: Unknown; U/M: EA; Value: 10uF; TaMax_C: 125°C; SizeZ_mm: 2.8; SizeX_mm: 3.2; SizeY_mm: 2.5; Cap_Case: 1210; SizeArea_mm2: 8; AEC Qualified: Y; Cap_F: 10µF; AEC Grade: 1; AEC Category: Q200
C30 C37 = CMP-0007139-4: CAP, CERM, 1 uF, 25 V, +/- 10%, X7R, AEC-Q200 Grade 1, 0603; Manufacturer: MuRata; TaMin_C: -55°C; Polarized: N; SizeAreaWB_mm2: 4.68; Value1: Unknown; U/M: EA; Value: 1uF; TaMax_C: 125°C; SizeZ_mm: 1; SizeX_mm: 1.6; SizeY_mm: 0.8; SizeArea_mm2: 1.28; AEC Qualified: Y; AEC Category: Q200
C58-C61 = CMP-0006483-1: CAP, CERM, 62 pF, 50 V, +/- 5%, C0G/NP0, 0402; Manufacturer: MuRata; TaMin_C: -55°C; Polarized: N; SizeAreaWB_mm2: 3; Value1: Unknown; U/M: EA; Value: 62pF; TaMax_C: 125°C; SizeZ_mm: 0.6; SizeX_mm: 1; SizeY_mm: 0.5; AEC Category: Q200
C62 C63 = CMP-0006289-1: CAP, CERM, 0.1 uF, 50 V, +/- 10%, X6S, 0402; Manufacturer: TDK; TaMin_C: -55°C; ESR_ohm: 39.064m; Polarized: N; SizeAreaWB_mm2: 3; Value1: 0.039064 ohm; U/M: EA; Value: 0.1uF; TaMax_C: 105°C; SizeZ_mm: 0.6; SizeX_mm: 1; SizeY_mm: 0.5; Cap_F: 100nF; IRMS_A: 814.669mA; AEC Category: Q200
D1 D3 D4 D6 = CMP-0090247-1: Diode Schottky 60V 2A Surface Mount CFP3; Manufacturer: Nexperia; PartNumber: PMEG6020ELRX; Cap_F: 110pF; SizeZ_mm: 1.1mm; TJmax_C: 175°C; AEC Grade: Grade 0; Forward Current: 2.83A; Max Surge Forward Current: 50A; AEC Qualified: Yes; TaMin_C: -55°C; Peak Reverse Current: 0.09uA; TaMax_C: +175°C
D2 D5 = CMP-0084402-3: Diode, Zener, 18 V, 500 mW, AEC-Q101, SOD-123; Manufacturer: Diodes Inc.; SizeX_mm: 3.85; SizeAreaWB_mm2: 13.095; Green_REACh: Incomplete; AEC Category: Q101; AEC Qualified: Y; Value1: 0.5W; SizeY_mm: 1.7; Power_W: 500mW; SizeZ_mm: 1.35; RJA_CperW: 338; SizeArea_mm2: 6.545; Green_Lifecycle: Active
GNDLV GNDLVF ISO15VGND ISO15VSW = CMP-0055143-1: as GND_LV on sheet PMP31182_SN6507_PWM
ISO15VH ISO15VL = CMP-0055142-1: as HVIN on sheet PMP31182_SN6507_PWM
J6 = CMP-0054974-1: Terminal Block, 2x1, 2.54mm, TH; Manufacturer: TE Connectivity; CNHeader: FALSE; Green_Lifecycle: Active; Green_REACh: Passed; CT: TRUE
L3 = CMP-0060122-1: Inductor, Wirewound, Ferrite, 240 nH, 0.85 A, 0.119999 ohm, SMD; Manufacturer: Coilcraft; PartNumber: 0603AF-241KRB; Irms: 0.85A @ 15C rise; Green_Lifecycle: Not Set; SizeAreaWB_mm2: 5.936; DCR_ohm: 1.19999d; Green_REACh: Incomplete; Value: 240nH; Imax_A: 8.5dA; SizeZ_mm: 0.91; SizeX_mm: 1.8; SizeY_mm: 1.12; Value2: 0.85A; SizeArea_mm2: 2.016; AEC Category: Q200
L4 L5 = CMP-0090488-1: 2 Line Common Mode Choke Surface Mount 90 Ohms @ 100MHz 400mA DCR 190mOhm; Manufacturer: TDK; SizeZ_mm: 1.3mm; DCR_ohm: 0.19; AEC Qualified: Yes; AEC Grade: Grade 2; Impedance At Frequency: 90Ω @ 100MHz
L6 L7 = CMP-0094235-1: 33 µH Shielded Molded Inductor 500 mA 1.33Ohm Max 1212 (3030 Metric); Manufacturer: Wurth; AEC Qualified: Yes; Test Frequency: 100kHz; Material: Magnetic Iron Alloy; Shrouded: true; TaMax_C: +85°C; TaMin_C: -40°C; AEC Grade: Grade 1; Value: 33uH; Irms: 0.5A; SizeZ_mm: 1.5mm; DCR_ohm: 1.33; Self Resonant Frequency: 10MHz; Tolerance_%: 20%; Isat: 1.3A; Ind_H: 33µH
R4 R9 R24 R27 R31 = CMP-0089143-1: as R18 on sheet PMP31182_SN6507_GaN
R8 R26 = CMP-0024440-2: RES, 6.81 k, 0.1%, 0.1 W, 0603; Manufacturer: Yageo America; Power_W: 100mW; TempCo: 25 ppm/C; Value_Code: 6k81; U/M: EA; Value: 6.81k; EIA_Code: E192; SizeX_mm: 1.6; SizeY_mm: 0.8; SizeZ_mm: 1; Value2: 0.1W; SizeArea_mm2: 1.28; VDC_V: 75V; AEC Category: Q200
R11 = CMP-0022714-3: RES, 0.33, 1%, 0.1 W, AEC-Q200 Grade 0, 0603; Manufacturer: Panasonic; Power_W: 100mW; TempCo: 300 ppm/C; Value_Code: R330; Value: 0.33; EIA_Code: E96; SizeX_mm: 1.6; SizeY_mm: 0.8; SizeZ_mm: 1; Value2: 0.1W; SizeArea_mm2: 1.28; AEC Qualified: Y; AEC Category: Q200; AEC Grade: 0; SizeAreaWB_mm2: 4.68
R13 R28 = CMP-0023919-2: RES, 1.00 k, 0.1%, 0.1 W, 0603; Manufacturer: Yageo America; Power_W: 100mW; TempCo: 25 ppm/C; Value_Code: 1k00; U/M: EA; Value: 1.00k; EIA_Code: E192; Res_ohm: 1k; SizeX_mm: 1.6; SizeY_mm: 0.8; SizeZ_mm: 1; Value2: 0.1W; SizeArea_mm2: 1.28; VDC_V: 75V; AEC Category: Q200
R23 R30 = CMP-0024307-2: RES, 50.5 k, 0.1%, 0.1 W, 0603; Manufacturer: Yageo America; Power_W: 100mW; TempCo: 25 ppm/C; Value_Code: 50k5; U/M: EA; Value: 50.5k; EIA_Code: E192; SizeX_mm: 1.6; SizeY_mm: 0.8; SizeZ_mm: 1; Value2: 0.1W; SizeArea_mm2: 1.28; VDC_V: 75V; AEC Category: Q200
R25 R32 = CMP-0023919-2: R; Manufacturer: Yageo America; PartNumber: RT0603BRD071KL; Power_W: 100mW; TempCo: 25 ppm/C; Value_Code: 1k00; Value1: 0.1%; U/M: EA; Value: 1.00k; EIA_Code: E192; Res_ohm: 1k; SizeX_mm: 1.6; SizeY_mm: 0.8; SizeZ_mm: 1; Value2: 0.1W; SizeArea_mm2: 1.28; VDC_V: 75V; AEC Category: Q200
R29 R42 = CMP-0022914-5: RES, 21.0 k, 1%, 0.1 W, 0603; Manufacturer: Yageo; Power_W: 100mW; TempCo: 100 ppm/C; Value_Code: 21k0; Value: 21.0k; EIA_Code: E96; Res_ohm: 21k; SizeX_mm: 1.6; SizeY_mm: 0.8; SizeZ_mm: 1; Value2: 0.1W; SizeArea_mm2: 1.28; AEC Qualified: N; VDC_V: 75V; AEC Category: Q200; SizeAreaWB_mm2: 4.68
R43 R45 = CMP-0023640-2: RES, 106 k, 0.1%, 0.1 W, 0603; Manufacturer: Yageo America; Power_W: 100mW; TempCo: 25 ppm/C; U/M: EA; Value: 106k; EIA_Code: E192; SizeX_mm: 1.6; SizeY_mm: 0.8; SizeZ_mm: 1; Value2: 0.1W; SizeArea_mm2: 1.28; VDC_V: 75V; AEC Category: Q200
R46-R49 = CMP-0026763-1: RES, 100, 1%, 0.063 W, AEC-Q200 Grade 0, 0402; Manufacturer: Stackpole Electronics Inc; Power_W: 63mW; TempCo: 100 ppm/C; Value_Code: 100R; U/M: EA; Value: 100; EIA_Code: E96; SizeX_mm: 1; SizeY_mm: 0.5; SizeZ_mm: 0.6; Value2: 0.063W; AEC Qualified: Y; AEC Grade: 0; AEC Category: Q200
T1 T2 = CMP-0095871-1: Push-Pull Transformers for Texas Instruments SN6507 Push Pull Driver; Manufacturer: Coilcraft; PartNumber: TX1-ZB1459-BED; SizeZ_mm: 5.97mm; Ns1toNp: 1:0.71; Frequency_Fixed: 1MHz; AEC Qualified: No; TaMax_C: +125°C; TaMin_C: -40°C; Ind_H: 196µH; Voltage_Isolation_Vrms: 2500Vrms; Rsec1_ohm: 98m; DCR_ohm: 0.115
U5 U6 = CMP-0095407-1: Low-Emission 36V Push-Pull Transformer Driver with Duty Cycle Control for Isolated Power Supplies; Manufacturer: Texas Instruments; AEC Qualified: No; TJmax_C: +150°C; TaMin_C: -55°C; TaMax_C: +125°C; Standoff Height: 0.05mm; SizeZ_mm: 1.1mm

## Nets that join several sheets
5V: PMP31182_SN6507_GaN (6 pins), PMP31182_SN6507_PWM (17 pins)
15V_F: PMP31182_SN6507_PWM (J7.1), PMP31182_SN6507_power_supply (18 pins)
GND_HV: PMP31182_SN6507_GaN (42 pins), PMP31182_SN6507_PWM (C49.2 GNDHV.1 J5.1), PMP31182_SN6507_power_supply (10 pins)
GND_LV: PMP31182_SN6507_GaN (12 pins), PMP31182_SN6507_PWM (23 pins), PMP31182_SN6507_power_supply (29 pins)
HVBUS: PMP31182_SN6507_GaN (24 pins), PMP31182_SN6507_PWM (C49.1 HVIN.1 J5.2)
ISO_15V_H: PMP31182_SN6507_GaN (R1.1), PMP31182_SN6507_power_supply (6 pins)
ISO_15V_L: PMP31182_SN6507_GaN (R3.1), PMP31182_SN6507_power_supply (6 pins)
Bot_FET_FAULT: PMP31182_SN6507_GaN (C57.1 R40.2), PMP31182_SN6507_PWM (C52.1 R14.1 U8.5)
Bot_FET_OC: PMP31182_SN6507_GaN (C56.1 R39.2), PMP31182_SN6507_PWM (C55.1 R17.1 U8.6)
Bot_FET_PWM: PMP31182_SN6507_GaN (R16.1), PMP31182_SN6507_PWM (R38.2)
SW: PMP31182_SN6507_GaN (50 pins), PMP31182_SN6507_power_supply (10 pins)
Top_FET_FAULT: PMP31182_SN6507_GaN (C40.1 R19.2), PMP31182_SN6507_PWM (C50.1 R10.1 U9.1)
Top_FET_OC: PMP31182_SN6507_GaN (C39.1 R20.2), PMP31182_SN6507_PWM (C51.1 R12.1 U9.2)
Top_FET_PWM: PMP31182_SN6507_GaN (R7.1), PMP31182_SN6507_PWM (R34.2 Top_FET_PWM.1)

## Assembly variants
001: all parts fitted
